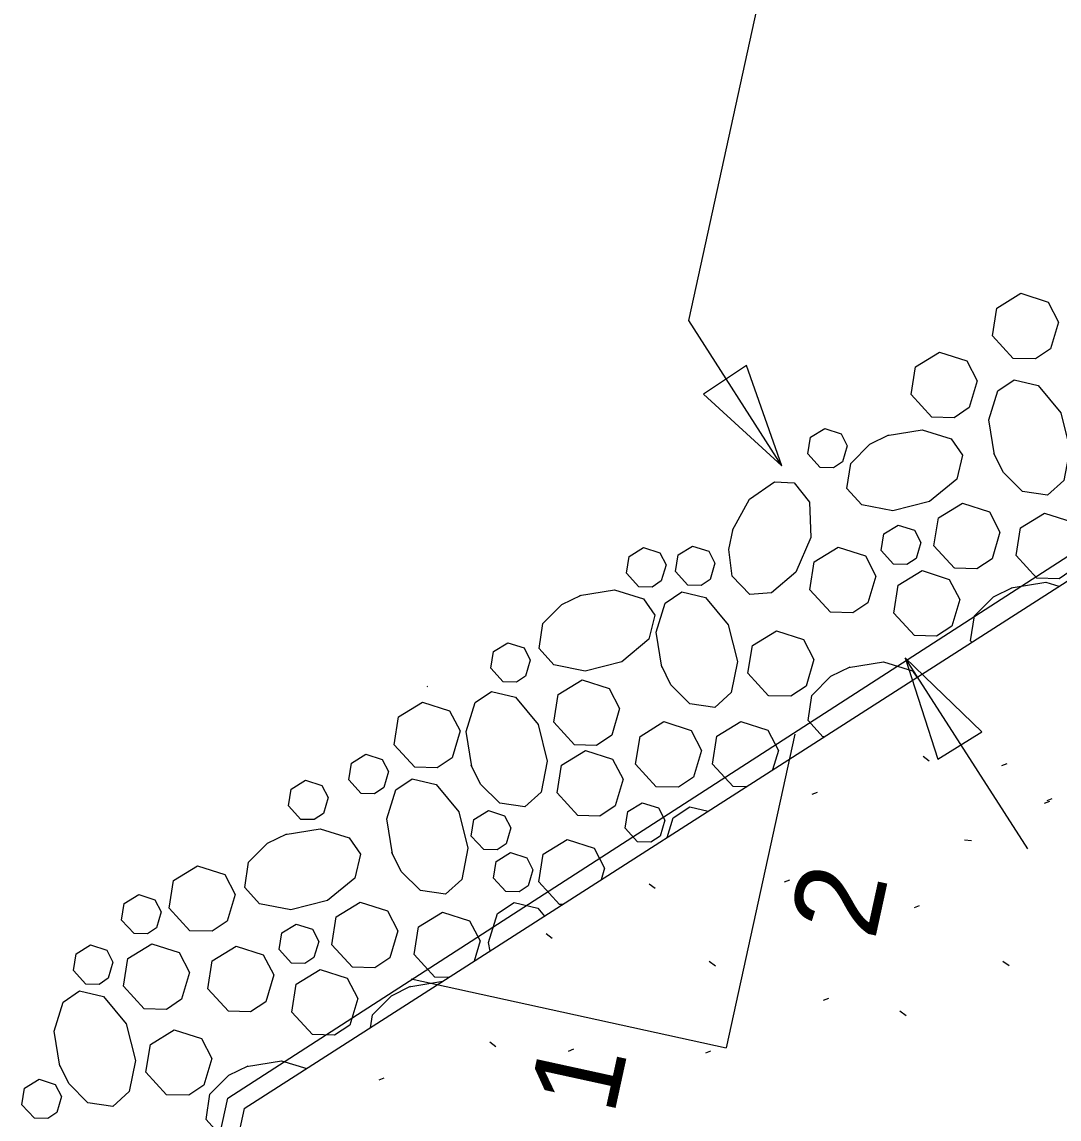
# Model space of a CAD drawing. Extents: x 2126110 to 2128246, y 1804858 to 1811658.
# Drawn here: x 2126731.1 to 2126790.5, y 1806355.9 to 1806418.7 of the extents above; entities that cross this region are included whole.
import ezdxf

# ---------------------------------------------------------------- set-up
doc = ezdxf.new("R2010")
doc.units = 0
doc.layers.add('1', color=7, linetype='Continuous')

msp = doc.modelspace()

# ---------------------------------------------------------------- linework, layer by layer
at = {"layer": '1'}
for p, q in [((2126769.294, 1806401.618), (2126773.341, 1806420.139)), ((2126742.894, 1806357.097), (2126821.033, 1806407.516)), ((2126743.847, 1806356.496), (2126822.044, 1806406.647)), ((2126774.631, 1806393.303), (2126769.294, 1806401.618)), ((2126788.708, 1806371.371), (2126781.693, 1806382.3)), ((2126754.346, 1806380.644), (2126754.322, 1806380.671)), ((2126775.364, 1806377.932), (2126771.44, 1806359.976)), ((2126783.06, 1806376.39), (2126782.707, 1806376.649)), ((2126787.216, 1806376.143), (2126787.515, 1806376.26)), ((2126772.572, 1806374.919), (2126771.834, 1806374.935)), ((2126776.366, 1806374.497), (2126776.664, 1806374.614)), ((2126789.671, 1806373.99), (2126789.969, 1806374.107)), ((2126789.808, 1806374.142), (2126790.106, 1806374.259)), ((2126785.082, 1806371.891), (2126785.482, 1806371.849)), ((2126774.777, 1806369.473), (2126775.075, 1806369.59)), ((2126767.37, 1806369.092), (2126767.018, 1806369.351)), ((2126762.067, 1806368.181), (2126761.887, 1806368.185)), ((2126782.213, 1806368.019), (2126782.511, 1806368.135)), ((2126761.476, 1806366.244), (2126761.124, 1806366.503)), ((2126770.816, 1806364.658), (2126770.463, 1806364.916)), ((2126787.633, 1806364.664), (2126787.28, 1806364.923)), ((2126753.274, 1806363.466), (2126755.21, 1806363.784)), ((2126753.394, 1806363.92), (2126771.44, 1806359.976)), ((2126755.552, 1806364.003), (2126754.754, 1806364.021)), ((2126777.016, 1806362.699), (2126777.314, 1806362.815)), ((2126781.739, 1806361.816), (2126781.386, 1806362.075)), ((2126758.257, 1806360.039), (2126757.904, 1806360.298)), ((2126762.413, 1806359.793), (2126762.712, 1806359.909)), ((2126770.262, 1806359.691), (2126770.56, 1806359.808)), ((2126751.563, 1806358.146), (2126751.861, 1806358.263)), ((2126764.868, 1806357.64), (2126765.166, 1806357.756)), ((2126765.005, 1806357.792), (2126765.303, 1806357.908)), ((2126736.789, 1806329.16), (2126742.894, 1806357.097)), ((2126743.847, 1806356.496), (2126738.017, 1806329.817))]:
    msp.add_line(p, q, dxfattribs=at)
for points in [[(2126787.871, 1806399.453), (2126786.685, 1806400.744), (2126786.939, 1806402.337), (2126788.312, 1806403.183), (2126789.866, 1806402.677), (2126790.462, 1806401.529), (2126790.01, 1806400.001), (2126789.142, 1806399.425), (2126787.872, 1806399.454)], [(2126783.216, 1806396.09), (2126782.029, 1806397.381), (2126782.284, 1806398.974), (2126783.656, 1806399.819), (2126785.21, 1806399.314), (2126785.806, 1806398.166), (2126785.355, 1806396.637), (2126784.486, 1806396.062), (2126783.217, 1806396.09)], [(2126786.799, 1806393.93), (2126786.471, 1806395.932), (2126786.988, 1806397.594), (2126787.928, 1806398.231), (2126789.297, 1806397.905), (2126790.59, 1806396.343), (2126791.122, 1806394.249), (2126790.765, 1806392.464), (2126789.834, 1806391.618), (2126788.396, 1806391.833), (2126787.307, 1806392.922), (2126786.768, 1806394.014)], [(2126776.818, 1806393.207), (2126776.106, 1806393.983), (2126776.258, 1806394.938), (2126777.082, 1806395.445), (2126778.015, 1806395.142), (2126778.372, 1806394.453), (2126778.1, 1806393.536), (2126777.58, 1806393.191), (2126776.818, 1806393.208)], [(2126780.66, 1806395.043), (2126782.663, 1806395.372), (2126784.324, 1806394.855), (2126784.962, 1806393.914), (2126784.636, 1806392.546), (2126783.074, 1806391.252), (2126780.98, 1806390.721), (2126779.194, 1806391.078), (2126778.349, 1806392.009), (2126778.564, 1806393.446), (2126779.653, 1806394.536), (2126780.745, 1806395.075)], [(2126771.806, 1806389.617), (2126772.774, 1806391.4), (2126774.201, 1806392.396), (2126775.335, 1806392.322), (2126776.216, 1806391.226), (2126776.28, 1806389.199), (2126775.416, 1806387.219), (2126774.04, 1806386.028), (2126772.786, 1806385.929), (2126771.782, 1806386.981), (2126771.589, 1806388.509), (2126771.833, 1806389.703)], [(2126784.518, 1806387.438), (2126783.332, 1806388.729), (2126783.586, 1806390.321), (2126784.958, 1806391.168), (2126786.513, 1806390.662), (2126787.109, 1806389.514), (2126786.657, 1806387.985), (2126785.789, 1806387.41), (2126784.519, 1806387.438)], [(2126789.225, 1806386.868), (2126788.038, 1806388.16), (2126788.293, 1806389.753), (2126789.665, 1806390.598), (2126791.219, 1806390.093), (2126791.815, 1806388.945), (2126791.363, 1806387.416), (2126790.495, 1806386.84), (2126789.225, 1806386.869)], [(2126781.023, 1806387.676), (2126780.311, 1806388.451), (2126780.463, 1806389.406), (2126781.287, 1806389.913), (2126782.219, 1806389.611), (2126782.577, 1806388.921), (2126782.305, 1806388.004), (2126781.784, 1806387.659), (2126781.023, 1806387.676)], [(2126766.44, 1806386.381), (2126765.728, 1806387.156), (2126765.88, 1806388.111), (2126766.704, 1806388.619), (2126767.636, 1806388.316), (2126767.994, 1806387.626), (2126767.723, 1806386.709), (2126767.202, 1806386.364), (2126766.44, 1806386.382)], [(2126769.24, 1806386.475), (2126768.528, 1806387.25), (2126768.681, 1806388.205), (2126769.504, 1806388.713), (2126770.437, 1806388.41), (2126770.794, 1806387.721), (2126770.523, 1806386.803), (2126770.002, 1806386.458), (2126769.24, 1806386.476)], [(2126777.411, 1806384.918), (2126776.225, 1806386.21), (2126776.479, 1806387.802), (2126777.852, 1806388.648), (2126779.406, 1806388.143), (2126780.002, 1806386.994), (2126779.55, 1806385.466), (2126778.681, 1806384.89), (2126777.411, 1806384.919)], [(2126782.217, 1806383.579), (2126781.031, 1806384.87), (2126781.285, 1806386.463), (2126782.657, 1806387.308), (2126784.212, 1806386.803), (2126784.808, 1806385.655), (2126784.356, 1806384.126), (2126783.487, 1806383.55), (2126782.218, 1806383.58)], [(2126787.745, 1806386.314), (2126789.747, 1806386.643), (2126790.492, 1806386.411)], [(2126763.041, 1806385.872), (2126765.044, 1806386.2), (2126766.705, 1806385.684), (2126767.342, 1806384.743), (2126767.017, 1806383.375), (2126765.454, 1806382.08), (2126763.36, 1806381.55), (2126761.575, 1806381.907), (2126760.729, 1806382.837), (2126760.944, 1806384.275), (2126762.033, 1806385.364), (2126763.126, 1806385.903)], [(2126767.76, 1806381.78), (2126767.432, 1806383.783), (2126767.948, 1806385.444), (2126768.888, 1806386.081), (2126770.257, 1806385.756), (2126771.551, 1806384.193), (2126772.083, 1806382.1), (2126771.725, 1806380.314), (2126770.794, 1806379.469), (2126769.357, 1806379.683), (2126768.267, 1806380.772), (2126767.728, 1806381.865)], [(2126785.498, 1806383.208), (2126785.433, 1806383.279), (2126785.648, 1806384.717), (2126786.737, 1806385.807), (2126787.83, 1806386.346)], [(2126773.868, 1806380.133), (2126772.683, 1806381.424), (2126772.936, 1806383.017), (2126774.309, 1806383.863), (2126775.863, 1806383.357), (2126776.459, 1806382.209), (2126776.007, 1806380.681), (2126775.139, 1806380.105), (2126773.869, 1806380.134)], [(2126758.666, 1806380.938), (2126757.954, 1806381.714), (2126758.107, 1806382.669), (2126758.93, 1806383.176), (2126759.862, 1806382.873), (2126760.22, 1806382.184), (2126759.949, 1806381.267), (2126759.428, 1806380.922), (2126758.666, 1806380.939)], [(2126778.444, 1806381.757), (2126780.447, 1806382.085), (2126782.108, 1806381.569), (2126782.361, 1806381.196)], [(2126777.036, 1806377.781), (2126776.978, 1806377.793), (2126776.132, 1806378.723), (2126776.347, 1806380.16), (2126777.436, 1806381.25), (2126778.529, 1806381.789)], [(2126762.747, 1806377.325), (2126761.56, 1806378.616), (2126761.814, 1806380.209), (2126763.187, 1806381.055), (2126764.741, 1806380.549), (2126765.337, 1806379.401), (2126764.885, 1806377.873), (2126764.016, 1806377.297), (2126762.747, 1806377.326)], [(2126756.869, 1806376.08), (2126756.542, 1806378.083), (2126757.058, 1806379.743), (2126757.999, 1806380.381), (2126759.367, 1806380.056), (2126760.662, 1806378.493), (2126761.192, 1806376.399), (2126760.835, 1806374.614), (2126759.905, 1806373.768), (2126758.467, 1806373.983), (2126757.378, 1806375.072), (2126756.839, 1806376.165)], [(2126753.61, 1806376.043), (2126752.423, 1806377.334), (2126752.677, 1806378.927), (2126754.05, 1806379.773), (2126755.604, 1806379.268), (2126756.2, 1806378.119), (2126755.748, 1806376.591), (2126754.879, 1806376.015), (2126753.61, 1806376.044)], [(2126767.435, 1806374.925), (2126766.249, 1806376.216), (2126766.503, 1806377.808), (2126767.876, 1806378.654), (2126769.43, 1806378.148), (2126770.026, 1806377), (2126769.574, 1806375.472), (2126768.706, 1806374.896), (2126767.436, 1806374.925)], [(2126771.833, 1806374.935), (2126770.647, 1806376.226), (2126770.901, 1806377.818), (2126772.274, 1806378.664), (2126773.828, 1806378.159), (2126774.424, 1806377.01), (2126774.094, 1806375.894)], [(2126762.939, 1806373.279), (2126761.753, 1806374.571), (2126762.007, 1806376.164), (2126763.379, 1806377.009), (2126764.934, 1806376.504), (2126765.53, 1806375.356), (2126765.078, 1806373.827), (2126764.209, 1806373.251), (2126762.94, 1806373.281)], [(2126750.544, 1806374.545), (2126749.832, 1806375.32), (2126749.985, 1806376.276), (2126750.808, 1806376.783), (2126751.741, 1806376.48), (2126752.098, 1806375.791), (2126751.827, 1806374.874), (2126751.306, 1806374.528), (2126750.544, 1806374.546)], [(2126747.09, 1806373.06), (2126746.379, 1806373.835), (2126746.531, 1806374.79), (2126747.355, 1806375.297), (2126748.287, 1806374.995), (2126748.645, 1806374.305), (2126748.374, 1806373.388), (2126747.853, 1806373.043), (2126747.091, 1806373.06)], [(2126752.328, 1806371.082), (2126752, 1806373.084), (2126752.517, 1806374.745), (2126753.458, 1806375.383), (2126754.826, 1806375.057), (2126756.12, 1806373.494), (2126756.651, 1806371.401), (2126756.294, 1806369.616), (2126755.363, 1806368.769), (2126753.926, 1806368.985), (2126752.836, 1806370.074), (2126752.297, 1806371.166)], [(2126766.366, 1806371.775), (2126765.655, 1806372.55), (2126765.807, 1806373.505), (2126766.631, 1806374.013), (2126767.563, 1806373.71), (2126767.921, 1806373.021), (2126767.65, 1806372.103), (2126767.129, 1806371.758), (2126766.367, 1806371.776)], [(2126757.556, 1806371.329), (2126756.844, 1806372.104), (2126756.996, 1806373.059), (2126757.82, 1806373.567), (2126758.752, 1806373.264), (2126759.11, 1806372.575), (2126758.839, 1806371.657), (2126758.318, 1806371.312), (2126757.556, 1806371.33)], [(2126768.058, 1806372.023), (2126768.407, 1806373.146), (2126769.348, 1806373.784), (2126770.409, 1806373.531)], [(2126746.19, 1806372.195), (2126748.192, 1806372.524), (2126749.853, 1806372.007), (2126750.491, 1806371.066), (2126750.165, 1806369.698), (2126748.603, 1806368.404), (2126746.509, 1806367.873), (2126744.724, 1806368.23), (2126743.878, 1806369.16), (2126744.093, 1806370.598), (2126745.182, 1806371.687), (2126746.275, 1806372.226)], [(2126761.886, 1806368.184), (2126760.7, 1806369.476), (2126760.954, 1806371.068), (2126762.326, 1806371.914), (2126763.881, 1806371.408), (2126764.477, 1806370.26), (2126764.282, 1806369.602)], [(2126758.821, 1806368.923), (2126758.109, 1806369.698), (2126758.262, 1806370.653), (2126759.085, 1806371.161), (2126760.018, 1806370.858), (2126760.375, 1806370.168), (2126760.104, 1806369.251), (2126759.583, 1806368.906), (2126758.821, 1806368.924)], [(2126740.728, 1806366.676), (2126739.542, 1806367.967), (2126739.796, 1806369.56), (2126741.169, 1806370.406), (2126742.723, 1806369.901), (2126743.319, 1806368.752), (2126742.866, 1806367.224), (2126741.998, 1806366.648), (2126740.729, 1806366.677)], [(2126737.534, 1806366.513), (2126736.822, 1806367.288), (2126736.975, 1806368.244), (2126737.798, 1806368.751), (2126738.731, 1806368.448), (2126739.089, 1806367.759), (2126738.817, 1806366.842), (2126738.297, 1806366.496), (2126737.534, 1806366.514)], [(2126750.047, 1806364.589), (2126748.862, 1806365.881), (2126749.115, 1806367.473), (2126750.488, 1806368.319), (2126752.042, 1806367.814), (2126752.638, 1806366.666), (2126752.186, 1806365.137), (2126751.318, 1806364.561), (2126750.048, 1806364.59)], [(2126757.914, 1806365.518), (2126757.835, 1806366), (2126758.352, 1806367.66), (2126759.292, 1806368.298), (2126760.661, 1806367.972), (2126761.035, 1806367.519)], [(2126754.754, 1806364.02), (2126753.568, 1806365.312), (2126753.822, 1806366.904), (2126755.194, 1806367.75), (2126756.748, 1806367.245), (2126757.344, 1806366.096), (2126757, 1806364.932)], [(2126746.552, 1806364.827), (2126745.84, 1806365.602), (2126745.992, 1806366.558), (2126746.816, 1806367.065), (2126747.748, 1806366.762), (2126748.106, 1806366.073), (2126747.834, 1806365.156), (2126747.313, 1806364.811), (2126746.552, 1806364.828)], [(2126734.769, 1806363.627), (2126734.057, 1806364.402), (2126734.21, 1806365.357), (2126735.033, 1806365.864), (2126735.966, 1806365.561), (2126736.324, 1806364.872), (2126736.052, 1806363.955), (2126735.531, 1806363.61), (2126734.769, 1806363.627)], [(2126738.117, 1806362.206), (2126736.931, 1806363.497), (2126737.184, 1806365.09), (2126738.558, 1806365.936), (2126740.112, 1806365.43), (2126740.707, 1806364.281), (2126740.255, 1806362.754), (2126739.387, 1806362.178), (2126738.117, 1806362.207)], [(2126742.941, 1806362.07), (2126741.754, 1806363.362), (2126742.008, 1806364.953), (2126743.381, 1806365.8), (2126744.935, 1806365.294), (2126745.531, 1806364.146), (2126745.079, 1806362.617), (2126744.21, 1806362.042), (2126742.941, 1806362.07)], [(2126747.746, 1806360.731), (2126746.561, 1806362.022), (2126746.814, 1806363.615), (2126748.187, 1806364.46), (2126749.741, 1806363.955), (2126750.337, 1806362.806), (2126749.885, 1806361.278), (2126749.017, 1806360.702), (2126747.747, 1806360.732)], [(2126733.289, 1806358.932), (2126732.961, 1806360.935), (2126733.477, 1806362.595), (2126734.418, 1806363.233), (2126735.786, 1806362.908), (2126737.081, 1806361.345), (2126737.612, 1806359.251), (2126737.254, 1806357.466), (2126736.324, 1806356.62), (2126734.887, 1806356.834), (2126733.796, 1806357.924), (2126733.258, 1806359.017)], [(2126751.066, 1806361.126), (2126751.177, 1806361.869), (2126752.266, 1806362.958), (2126753.359, 1806363.497)], [(2126739.398, 1806357.285), (2126738.212, 1806358.576), (2126738.466, 1806360.169), (2126739.838, 1806361.014), (2126741.392, 1806360.509), (2126741.988, 1806359.361), (2126741.536, 1806357.833), (2126740.668, 1806357.257), (2126739.399, 1806357.286)], [(2126743.466, 1806354.752), (2126742.507, 1806354.944), (2126741.661, 1806355.875), (2126741.876, 1806357.312), (2126742.965, 1806358.402), (2126744.058, 1806358.941)], [(2126743.973, 1806358.909), (2126745.976, 1806359.237), (2126747.421, 1806358.788)], [(2126731.826, 1806355.939), (2126731.114, 1806356.713), (2126731.266, 1806357.669), (2126732.091, 1806358.177), (2126733.022, 1806357.873), (2126733.38, 1806357.185), (2126733.109, 1806356.267), (2126732.588, 1806355.922), (2126731.827, 1806355.939)]]:
    msp.add_lwpolyline(points, dxfattribs=at)
for points in [[(2126770.143, 1806397.416), (2126774.631, 1806393.303), (2126772.607, 1806399.044)], [(2126786.065, 1806378.063), (2126781.693, 1806382.3), (2126783.557, 1806376.504)]]:
    msp.add_lwpolyline(points, close=True, dxfattribs=at)

# ---------------------------------------------------------------- texts
for s, p in [('2', (2126779.938, 1806366.075)), ('1', (2126764.995, 1806356.036))]:
    msp.add_text(s, height=5, rotation=77.67359, dxfattribs=at).set_placement(p)

doc.saveas('drawing.dxf')
